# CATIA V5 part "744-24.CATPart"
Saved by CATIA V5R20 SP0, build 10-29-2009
Part number: 744-24
Revision: TUTTO
Definition: NON CONOSCIUTO
Nomenclature: 744-24
Source: Unknown
Bounding box of the stored display mesh (mm): x -24 to 24, y -25 to 23.825, z -23 to 36
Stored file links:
  C:\Users\Utente\Desktop\IO LAVORO\3D X SITO CF\X SITO\744\744-24.CATPart
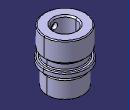
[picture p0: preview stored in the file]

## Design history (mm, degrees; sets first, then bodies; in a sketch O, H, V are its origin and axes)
Body1 "744-24 sol1" (main body)
  Solid1: solid without history
Body2 "IDV1M8_Ingrassatore-1"
  Solid2: solid without history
